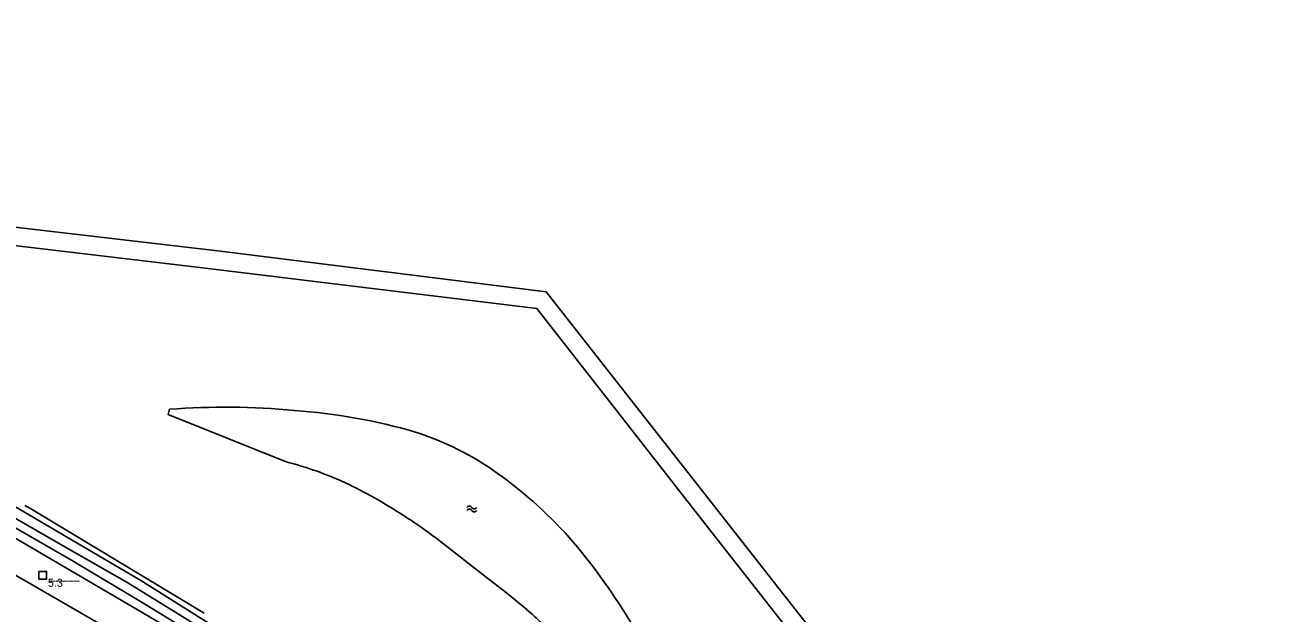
# Model space of a CAD drawing. Extents: x 133000 to 136000, y 400500 to 403500.
# Drawn here: x 134801.3 to 134995, y 400991.7 to 401083.5 of the extents above; entities that cross this region are included whole.
import ezdxf

# ---------------------------------------------------------------- set-up
doc = ezdxf.new("R2010")
doc.units = 0
for name, color, linetype in [('gg-afsc-erfafscheiding', 7, 'Continuous'), ('gg-anno-openbare ruimte label', 7, 'Continuous'), ('gg-knt-verharding', 7, 'Continuous'), ('gg-kntw-bovenkant insteek waterloop', 7, 'Continuous'), ('gg-kntw-waterlijn', 7, 'Continuous'), ('gt-anno-nummer hm paal', 7, 'Continuous'), ('gt-symb-hm paal', 7, 'Continuous'), ('gt-symb-watersymbool', 7, 'Continuous')]:
    doc.layers.add(name, color=color, linetype=linetype)

# ---------------------------------------------------------------- blocks, each defined once
blk = doc.blocks.new('gt0-HMpaal')
at = {"layer": 'gt-symb-hm paal'}
blk.add_lwpolyline([(-0.6, 0.6), (0.6, 0.6), (0.6, -0.6), (-0.6, -0.6)], close=True, dxfattribs=at)
blk = doc.blocks.new('gt0-WA')
at = {"layer": 'gt-symb-watersymbool'}
for centre, start, end in [((-0.32, 0.02), 28.0725, 151.9275), ((0.43, 0.42), 208.0725, 331.9275), ((-0.32, -0.43), 28.0725, 151.9275), ((0.43, -0.03), 208.0725, 331.9275)]:
    blk.add_arc(centre, 0.425, start, end, dxfattribs=at)

msp = doc.modelspace()

# ---------------------------------------------------------------- linework, layer by layer
at = {"layer": 'gg-afsc-erfafscheiding'}
for points in [[(135204.87, 400819.66), (135154.08, 400877.21), (135108.33, 400928.86), (135039.01, 400869.75), (135031.25, 400876.44), (135011, 400893.49), (134991.03, 400909.05), (134970.55, 400924.88), (134931.74, 400974.9), (134906.61, 401006.91), (134881.3, 401039.29), (134829.08, 401045.62), (134770.23, 401052.61), (134723.77, 401075.92), (134670.6, 401100.32), (134628.77, 401117.58), (134578.46, 401136.46), (134582.45, 401187.79), (134585.07, 401224), (134585.04, 401233.07)], [(134588.4, 401233.72), (134588.05, 401226.96), (134585.33, 401187.58), (134581.07, 401138.36), (134629.72, 401120.22), (134672.37, 401102.66), (134725.01, 401078.49), (134771.22, 401055.28), (134831.89, 401048.21), (134882.76, 401041.86), (134935.43, 400974.77), (134972.46, 400927.18), (134992.66, 400911.43), (135014.45, 400894.05), (135039.16, 400873.75), (135109.1, 400932.9), (135128.08, 400911.43)], [(134829.35, 400991.73), (134816.39, 400999.56), (134803.4, 401007.33), (134802.37, 401007.94), (134801.33, 401008.53)]]:
    msp.add_lwpolyline(points, dxfattribs=at)
at = {"layer": 'gg-knt-verharding'}
msp.add_lwpolyline([(135047.77, 400816.94), (135039.36, 400824.61), (135022.23, 400839.75), (135004.62, 400854.74), (134988.43, 400868.12), (134972.48, 400880.91), (134956.04, 400893.75), (134938.53, 400906.75), (134919.76, 400920.26), (134900.07, 400934.25), (134879.94, 400948), (134859.25, 400961.57), (134838.99, 400974.25), (134824.54, 400983.12), (134814.2, 400989.37), (134794.13, 401000.94), (134771.38, 401013.57), (134759.94, 401019.66)], dxfattribs=at)
at = {"layer": 'gg-kntw-bovenkant insteek waterloop'}
for points in [[(134572.77, 401113.87), (134593.26, 401106.65), (134614.36, 401098.39), (134636.05, 401089.52), (134662.13, 401078.83), (134682.97, 401068.98), (134701.81, 401060.06), (134721.13, 401050.34), (134741.39, 401039.88), (134760.64, 401029.96), (134779.82, 401019.57), (134800.39, 401008.03), (134819.43, 400996.83), (134838.42, 400984.94), (134877.76, 400959.96), (134896.36, 400947.62), (134928.35, 400924.84), (134948.77, 400909.72), (134968.04, 400895.55), (134985.71, 400881.7), (135003.43, 400867.53)], [(134999.15, 400865.39), (134983.55, 400878.24), (134965.57, 400892.51), (134948.44, 400905.63), (134930.21, 400918.86), (134909.59, 400933.18), (134896.02, 400942.64), (134877.47, 400955.17), (134859.24, 400967.08), (134841.26, 400978.65), (134823.05, 400989.84), (134797.2, 401004.96), (134777.3, 401016.05), (134757.03, 401026.72), (134733.14, 401038.94), (134701.13, 401054.6), (134682.13, 401063.5), (134663.52, 401072), (134638.58, 401082.34), (134619.62, 401090.08), (134592.99, 401100.44), (134572.42, 401107.64)], [(134842.15, 401015.36), (134823.71, 401022.74), (134823.92, 401023.55)], [(134865.77, 401003.27), (134869.59, 401000.34), (134873.36, 400997.36), (134876.55, 400994.88), (134879.7, 400992.33)]]:
    msp.add_lwpolyline(points, dxfattribs=at)
for centre, radius, start, end in [((134832.66, 400907.84), 116.04, 84.6656, 94.3192), ((134836.62, 400930.95), 92.68, 73.9009, 85.7764), ((134848.22, 400975.84), 46.35, 54.538, 72.2889), ((134827.83, 400960.22), 56.97, 65.5593, 75.4493), ((134814.78, 400936.64), 83.87, 57.1285, 64.1046), ((134834.9, 400957.44), 69.07, 40.9862, 54.3928), ((134820.35, 400943.78), 74.85, 52.6364, 57.7441), ((134814.33, 400941.24), 95.23, 30.7525, 40.2255), ((134808.94, 400912.57), 106.62, 44.8952, 48.4245)]:
    msp.add_arc(centre, radius, start, end, dxfattribs=at)
at = {"layer": 'gg-kntw-waterlijn'}
for points in [[(134788.76, 401012.89), (134806.22, 401002.88), (134817.4, 400996.47), (134830.22, 400988.55), (134846.36, 400978.57), (134857.44, 400971.52), (134879.17, 400957.32), (134894.75, 400947.15), (134904.21, 400940.53), (134912.63, 400934.81), (134918.23, 400930.69), (134925.52, 400925.59), (134934.62, 400919.23), (134939.57, 400915.46), (134950.59, 400907.34), (134963.57, 400897.45), (134978.12, 400885.91), (134993.2, 400873.96), (135008.25, 400861.04)], [(134999.53, 400867.09), (134990.79, 400874.23), (134984.06, 400879.73), (134970.7, 400890.51), (134952.89, 400904.22), (134943.87, 400910.95), (134934.96, 400917.45), (134921.02, 400927.24), (134907.08, 400937.04), (134896.34, 400944.58), (134885.84, 400951.58), (134877.84, 400956.75), (134868.59, 400962.71), (134858.63, 400969.14), (134846.46, 400977), (134820.18, 400993.09), (134808.91, 400999.83), (134798.33, 401005.96)]]:
    msp.add_lwpolyline(points, dxfattribs=at)

# ---------------------------------------------------------------- block references
at = {"layer": 'gt-symb-hm paal'}
msp.add_blockref('gt0-HMpaal', (134804.14, 400997.64), dxfattribs=at)
at = {"layer": 'gt-symb-watersymbool'}
msp.add_blockref('gt0-WA', (134871.07, 401008), dxfattribs=at)

# ---------------------------------------------------------------- texts
at = {"layer": 'gg-anno-openbare ruimte label'}
msp.add_text('Burgemeester Bechtweg', height=2.5, rotation=330, dxfattribs=at).set_placement((134769.72, 400994.13))
at = {"layer": 'gt-anno-nummer hm paal'}
msp.add_text('5.3', height=1.25, dxfattribs=at).set_placement((134804.94, 400995.85))
at = {"layer": 'gt-symb-hm paal'}
msp.add_text('_____', height=1.25, dxfattribs=at).set_placement((134805.23, 400997.03))

doc.saveas('drawing.dxf')
